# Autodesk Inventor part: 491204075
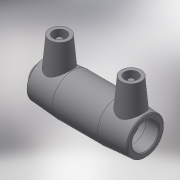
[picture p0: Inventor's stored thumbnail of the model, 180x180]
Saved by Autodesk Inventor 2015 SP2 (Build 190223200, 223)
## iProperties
Created: 2017-06
Part Number: 491204075
Material: Generic
Description: PLASSON END CAP 75
Document SubType Name: Modeling
Designer: KIM
Mass: 38.9236 g
Surface Area: 152.394 cm^2
Volume: 38.9236 cm^3
Density: 1 g/cm^3
Appearance: Default
Author: KIM
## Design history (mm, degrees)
derived "491204.ipt"
feature "Solid1::491204.ipt"
tag "TaggingFeature1"
body "Solid1"
other parameters: "d0" = 126, "d1" = 75, "d2" = 98, "d3" = 61, "d4" = 39, "d5" = 88.2, "d6" = 71.25, "d7" = 75, "d8" = 168 deg, "d10" = 24.4, "d11" = 8.13333, "d13" = 124.8, "d14" = 17.6296, "d15" = 61, "d16" = 61, "d17" = 71.25, "d18" = 75, "d19" = 3.52592, "d20" = 168 deg, "d22" = 92.12, "d23" = 98, "d24" = 89.3564, "d25" = 135 deg, "d26" = 56.16, "d27" = 135 deg, "d29" = 64, "d30" = 15, "d31" = 49.92, "d34" = 5 deg, "d35" = 15, "d39" = 5 deg, "d41" = 4, "d42" = 14, "d43" = 0, "d45" = 4, "d46" = 14, "d47" = 0, "d48" = 156, "d49" = 1, "d52" = 2.808, "d53" = 82.5, "d54" = 2.808, "d56" = 7.5, "d57" = 2.25, "d60" = 23.4, "d61" = 1.5, "d63" = 156, "d64" = 1, "d67" = 15, "d68" = 82.5, "d69" = 3.12, "d70" = 0, "d71" = 2.808, "d72" = 3, "d73" = 0, "d74" = 17.69, "d75" = 5.89667, "d76" = 3, "d77" = 0, "d_" = 75, "L_" = 156, "L_1" = 61, "D_" = 98, "A_" = 64, "d_2" = 12, "L_0" = 126, "d55" = 7.5
